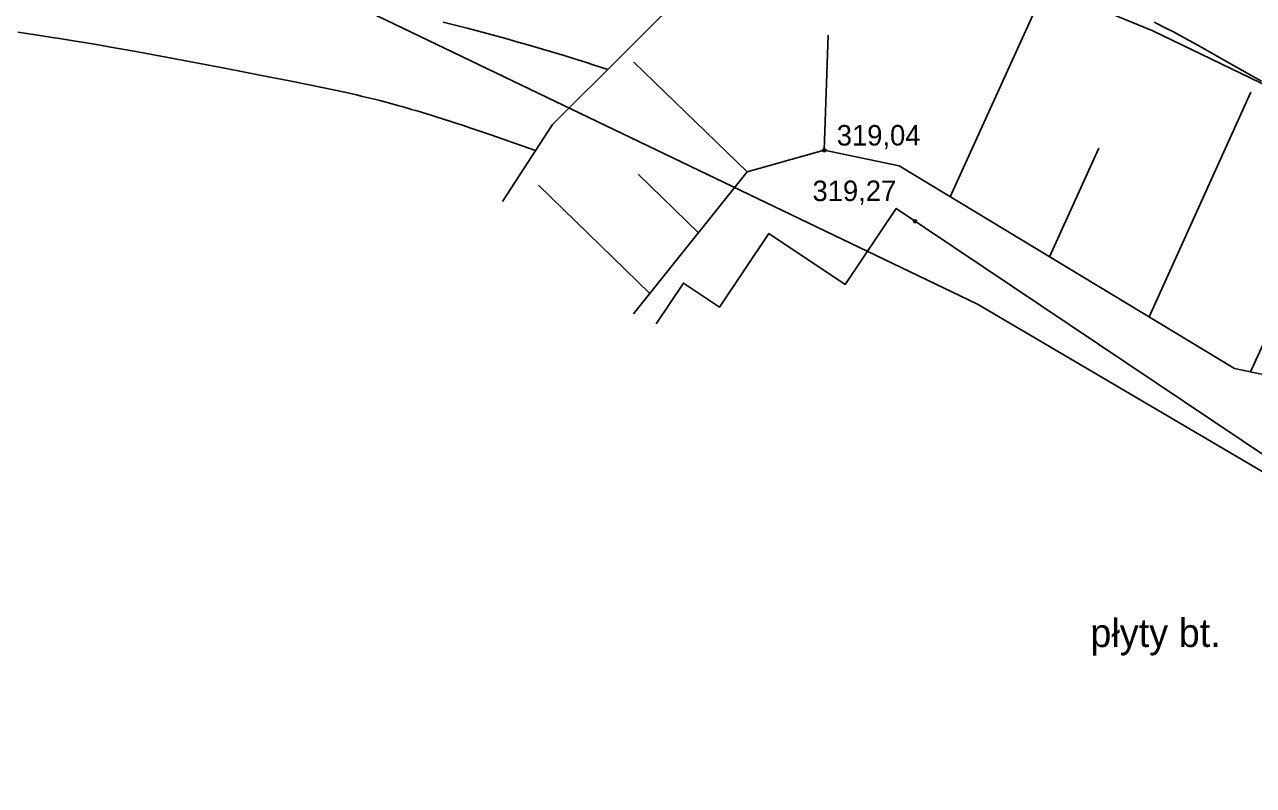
# Model space of a CAD drawing. Extents: x 7477803 to 7478145, y 5500698 to 5500984.
# Drawn here: x 7477904.37 to 7477945.16, y 5500753.51 to 5500778.77 of the extents above; entities that cross this region are included whole.
import ezdxf

# ---------------------------------------------------------------- set-up
doc = ezdxf.new("R2010")
doc.units = 0
for name, color, linetype in [('jezdnia', 7, 'Continuous'), ('opisy_drog', 7, 'Continuous'), ('pkt_wys', 7, 'Continuous'), ('skarp_wypel', 7, 'Continuous'), ('skarpa_dol', 7, 'Continuous'), ('skarpa_gora', 7, 'Continuous'), ('warst_pogrub', 7, 'Continuous'), ('warst_przeryw', 7, 'Continuous'), ('zakresy', 7, 'Continuous')]:
    doc.layers.add(name, color=color, linetype=linetype)

# ---------------------------------------------------------------- blocks, each defined once
blk = doc.blocks.new('801_5_3')
at = {"layer": 'pkt_wys'}
blk.add_circle((0, 0), 0.05, dxfattribs=at)
blk.add_circle((0, 0), 0.05, dxfattribs=at)

msp = doc.modelspace()

# ---------------------------------------------------------------- linework, layer by layer
at = {"layer": 'jezdnia'}
msp.add_lwpolyline([(7477992.069, 5500728.595), (7477992.586, 5500729.366), (7477990.061, 5500731.06), (7477991.702, 5500733.507), (7477933.306, 5500772.671), (7477931.61, 5500770.142), (7477929.08, 5500771.838), (7477927.439, 5500769.391), (7477926.244, 5500770.192), (7477925.336, 5500768.842)], dxfattribs=at)
at = {"layer": 'skarp_wypel'}
for p, q in [((7477935.1, 5500773.056), (7477938.156, 5500779.794)), ((7477930.919, 5500774.6), (7477931.047, 5500778.422)), ((7477928.36, 5500773.878), (7477924.598, 5500777.528)), ((7477941.697, 5500769.071), (7477945.079, 5500776.527)), ((7477938.398, 5500771.064), (7477940.036, 5500774.673)), ((7477926.743, 5500771.862), (7477924.742, 5500773.804)), ((7477925.126, 5500769.846), (7477921.426, 5500773.436)), ((7477945.07, 5500767.244), (7477946.982, 5500771.458))]:
    msp.add_line(p, q, dxfattribs=at)
at = {"layer": 'skarpa_dol'}
msp.add_lwpolyline([(7478003.179, 5500722.859), (7478004.323, 5500725.251), (7478005.298, 5500730.032), (7478003.066, 5500732.439), (7477998.881, 5500736.525), (7477989.029, 5500747.324), (7477982.233, 5500752.776), (7477973.187, 5500758.837), (7477956.935, 5500769.599), (7477950.58, 5500774.332), (7477941.825, 5500778.562), (7477933.581, 5500781.953), (7477926.713, 5500780.256), (7477921.899, 5500775.451), (7477920.234, 5500772.903)], dxfattribs=at)
at = {"layer": 'skarpa_gora'}
msp.add_lwpolyline([(7477924.585, 5500769.172), (7477928.36, 5500773.878), (7477930.919, 5500774.6), (7477933.4, 5500774.083), (7477944.537, 5500767.355), (7477948.908, 5500766.44), (7477961.969, 5500756.974), (7477978.9, 5500746.323), (7477991.003, 5500734.936), (7477993.436, 5500731.709), (7477996, 5500728.251), (7477997.928, 5500724.248)], dxfattribs=at)
at = {"layer": 'warst_pogrub'}
msp.add_lwpolyline([(7477918.27, 5500778.854), (7477918.8, 5500778.72), (7477919.068, 5500778.651), (7477919.61, 5500778.508), (7477920.344, 5500778.307), (7477920.717, 5500778.202), (7477920.998, 5500778.122), (7477921.376, 5500778.012), (7477921.566, 5500777.956), (7477922.278, 5500777.742), (7477922.598, 5500777.643), (7477923.028, 5500777.509), (7477923.244, 5500777.441), (7477923.735, 5500777.283)], dxfattribs=at)
at = {"layer": 'warst_przeryw'}
for points in [[(7477941.864, 5500778.851), (7477942.303, 5500778.63), (7477942.482, 5500778.538), (7477942.705, 5500778.422), (7477942.81, 5500778.367), (7477943.029, 5500778.249), (7477943.322, 5500778.086), (7477943.939, 5500777.733), (7477944.347, 5500777.501), (7477945.027, 5500777.12), (7477945.425, 5500776.898)], [(7477921.336, 5500774.59), (7477920.669, 5500774.821), (7477919.844, 5500775.11), (7477919.449, 5500775.247), (7477919.217, 5500775.326), (7477918.91, 5500775.429), (7477918.758, 5500775.479), (7477918.457, 5500775.577), (7477918.062, 5500775.702), (7477917.866, 5500775.763), (7477917.433, 5500775.893), (7477917.22, 5500775.956), (7477916.938, 5500776.037), (7477916.799, 5500776.076), (7477916.524, 5500776.151), (7477916.162, 5500776.247), (7477915.984, 5500776.293), (7477915.589, 5500776.39), (7477915.394, 5500776.436), (7477915.008, 5500776.524), (7477914.621, 5500776.608), (7477913.819, 5500776.773), (7477913.17, 5500776.902), (7477912.235, 5500777.086), (7477911.737, 5500777.183), (7477910.952, 5500777.334), (7477909.835, 5500777.546), (7477909.246, 5500777.656), (7477908.008, 5500777.886), (7477907.359, 5500778.002), (7477906.69, 5500778.118), (7477906.348, 5500778.176), (7477906.001, 5500778.233), (7477905.531, 5500778.309), (7477905.293, 5500778.346), (7477904.809, 5500778.42), (7477904.151, 5500778.518)]]:
    msp.add_lwpolyline(points, dxfattribs=at)
at = {"layer": 'zakresy'}
msp.add_lwpolyline([(7477995.059, 5500962.348), (7477983.951, 5500968.084), (7477970.781, 5500968.613), (7477936.09, 5500958.171), (7477930.511, 5500954.336), (7477914.305, 5500958.58), (7477904.32, 5500957.41), (7477897.265, 5500950.868), (7477811.424, 5500829.338), (7477936.003, 5500769.492), (7478008.982, 5500726.585), (7478019.402, 5500721.781), (7478037.95, 5500734.97), (7478039.493, 5500755.094), (7478043.98, 5500765.708), (7478067.545, 5500795.068), (7478092.109, 5500820.25), (7478076.156, 5500837.989), (7478068.105, 5500851.146), (7478061.422, 5500873.298), (7478054.135, 5500876.371), (7478039.669, 5500897.644), (7478026.36, 5500915.23), (7478015.054, 5500927.728)], close=True, dxfattribs=at)

# ---------------------------------------------------------------- block references
at = {"layer": 'pkt_wys', "rotation": 0.0626175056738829}
for p in [(7477930.919, 5500774.6), (7477933.932, 5500772.244)]:
    msp.add_blockref('801_5_3', p, dxfattribs=at)

# ---------------------------------------------------------------- texts
at = {"layer": 'opisy_drog'}
msp.add_text('płyty bt.', height=0.94, rotation=0.0626, dxfattribs=at).set_placement((7477939.748, 5500758.106))
at = {"layer": 'pkt_wys'}
for s, p in [('319,04', (7477931.331, 5500774.756)), ('319,27', (7477930.526, 5500772.912))]:
    msp.add_text(s, height=0.68, rotation=0.0626, dxfattribs=at).set_placement(p)

doc.saveas('drawing.dxf')
